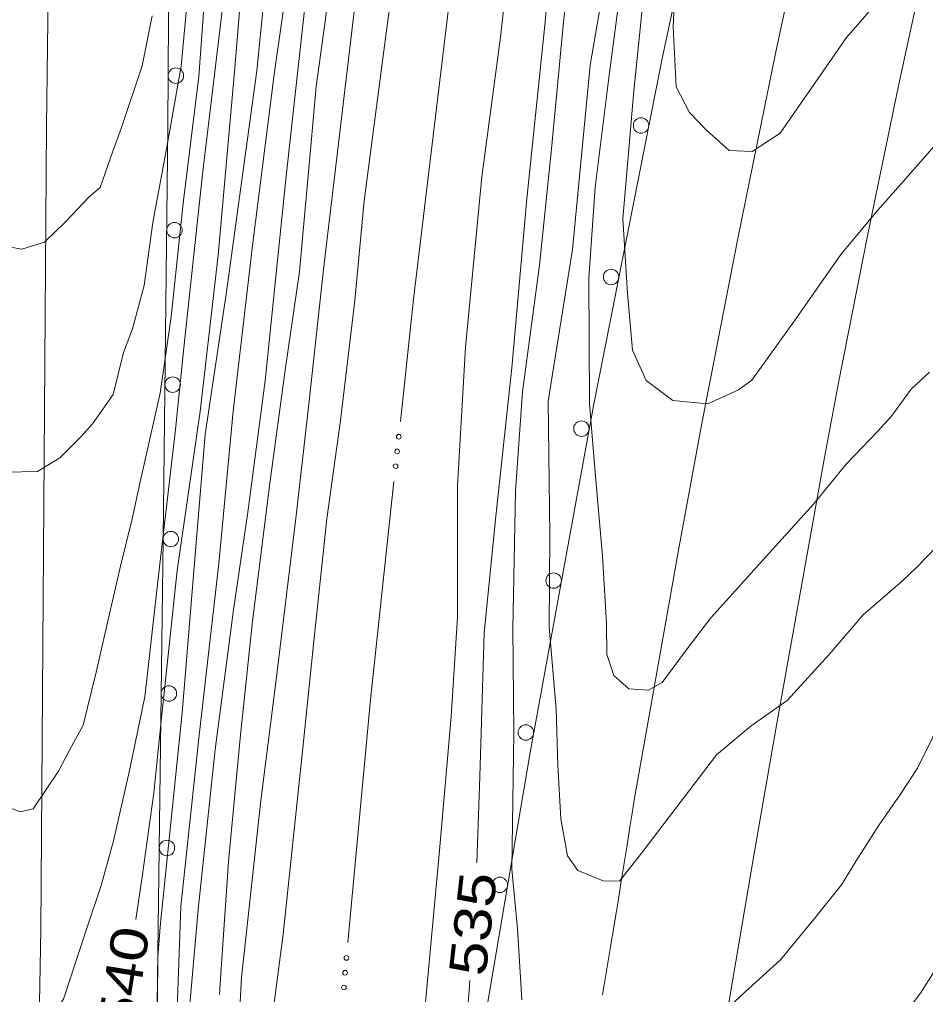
# Model space of a CAD drawing. Extents: x 2361284 to 2366480, y 6976556 to 6985346.
# Drawn here: x 2364474.8 to 2364592.1, y 6978408.5 to 6978534.7 of the extents above; entities that cross this region are included whole.
import ezdxf
from ezdxf.enums import TextEntityAlignment as Align

# ---------------------------------------------------------------- set-up
doc = ezdxf.new("R2010")
doc.units = 0
doc.header["$LTSCALE"] = 1.9
for name, color, linetype, lineweight in [('12', 7, 'Continuous', 13), ('13', 7, 'Continuous', 13), ('14', 7, 'Continuous', 13), ('17', 7, 'Continuous', 13), ('21', 7, 'Continuous', 13), ('3', 7, 'Continuous', 13)]:
    doc.layers.add(name, color=color, linetype=linetype, lineweight=lineweight)

msp = doc.modelspace()

# ---------------------------------------------------------------- linework, layer by layer
at = {"layer": '12'}
for points in [[(2364590.124, 6978796.473), (2364589.311, 6978793.616), (2364586.065, 6978781.543), (2364582.324, 6978764.768), (2364579.81, 6978751.442), (2364577.506, 6978732.98), (2364572.929, 6978712.785), (2364567.408, 6978685.481), (2364562.208, 6978655.901), (2364557.098, 6978625.39), (2364552.346, 6978600.353), (2364548.188, 6978577.113), (2364544.913, 6978557.55), (2364542.796, 6978533.969), (2364540.48, 6978511.486), (2364538.538, 6978489.626), (2364536.45, 6978470.414), (2364534.954, 6978455.27), (2364534.391, 6978436.674), (2364534.007, 6978425.489)], [(2364535.587, 6978743.233), (2364536.974, 6978737.144), (2364537.8, 6978722.852), (2364537.862, 6978705.811), (2364536.854, 6978695.091), (2364536.006, 6978686.533), (2364533.867, 6978665.382), (2364530.209, 6978635.716), (2364527.935, 6978616.122), (2364525.352, 6978597.457), (2364523.812, 6978581.63), (2364522.159, 6978564.185), (2364518.517, 6978539.078), (2364516.417, 6978521.208), (2364514.146, 6978502.345), (2364512.272, 6978484.886), (2364510.629, 6978470.469), (2364507.927, 6978448.502), (2364506.029, 6978433.584), (2364503.557, 6978410.64), (2364503.325, 6978406.647)], [(2364520.506, 6978735.888), (2364521.366, 6978731.636), (2364522.041, 6978723.722), (2364521.873, 6978713.01), (2364521.202, 6978704.803), (2364519.868, 6978691.46), (2364518.363, 6978678.275), (2364516.741, 6978664.799), (2364515.812, 6978651.079), (2364514.09, 6978638.611), (2364511.3, 6978619.744), (2364510.213, 6978597.243), (2364508.054, 6978577.141), (2364505.377, 6978557.884), (2364503.673, 6978540.488), (2364502.652, 6978527.957), (2364500.508, 6978504.195), (2364498.169, 6978483.972), (2364495.205, 6978463.383), (2364493.197, 6978444.292), (2364492.189, 6978434.553), (2364490.673, 6978423.687), (2364489.845, 6978418.159)], [(2364588.977, 6978540.589), (2364581.863, 6978532.4), (2364573.302, 6978519.989), (2364569.644, 6978517.604), (2364566.703, 6978517.736), (2364563.737, 6978520.368), (2364561.545, 6978522.667), (2364559.823, 6978525.99), (2364559.439, 6978533.787), (2364559.824, 6978542.732)], [(2364630.041, 6978541.409), (2364626.113, 6978529.581), (2364621.172, 6978517.023), (2364616.554, 6978502.098), (2364611.573, 6978484.27), (2364607.524, 6978469.281), (2364604.843, 6978459.045), (2364602.326, 6978447.1), (2364599.597, 6978433.284), (2364597.875, 6978424.076), (2364596.63, 6978419.294), (2364595.576, 6978416.524), (2364594.727, 6978414.336), (2364593.304, 6978411.563), (2364591.441, 6978408.625), (2364589.328, 6978405.834)], [(2364533.102, 6978410.281), (2364533.008, 6978408.979), (2364532.788, 6978406.379)]]:
    msp.add_lwpolyline(points, dxfattribs=at)
at = {"layer": '13'}
for points in [[(2364539.856, 6978407.775), (2364539.268, 6978416.999), (2364538.525, 6978424.672), (2364538.797, 6978442.385), (2364538.679, 6978455.856), (2364539.02, 6978473.66), (2364539.918, 6978486.509), (2364542.122, 6978502.901), (2364543.699, 6978517.987), (2364545.289, 6978534.842), (2364548.165, 6978556.391), (2364551.398, 6978579.073), (2364553.046, 6978586.639), (2364558.044, 6978612.148), (2364562.074, 6978637.429), (2364565.198, 6978653.839), (2364569.218, 6978674.988), (2364572.691, 6978692.602), (2364576.99, 6978711.574), (2364581.098, 6978731.754), (2364583.754, 6978746.931), (2364586.385, 6978763.626), (2364588.318, 6978773.935), (2364590.919, 6978788.541)], [(2364582.984, 6978780.554), (2364580.379, 6978769.43), (2364576.587, 6978750.812), (2364573.957, 6978736.106), (2364570.838, 6978720.207), (2364567.142, 6978699.83), (2364561.372, 6978672.302), (2364558.398, 6978655.884), (2364553.047, 6978628.662), (2364548.88, 6978607.382), (2364543.311, 6978577.796), (2364539.917, 6978558.062), (2364537.061, 6978532.444), (2364534.643, 6978514.34), (2364532.562, 6978492.269), (2364531.503, 6978474.349), (2364531.525, 6978457.318), (2364530.707, 6978444.469), (2364529.182, 6978427.093), (2364527.257, 6978406.534)], [(2364518.057, 6978768.387), (2364518.855, 6978766.494), (2364521.169, 6978759.735), (2364524.687, 6978750.488), (2364527.432, 6978743.715), (2364530.833, 6978734.076), (2364532.199, 6978721.908), (2364531.854, 6978712.945), (2364531.128, 6978696.817), (2364529.226, 6978679.108), (2364526.23, 6978658.639), (2364523.037, 6978629.497), (2364520.35, 6978610.32), (2364516.514, 6978581.462), (2364514.849, 6978568.325), (2364512.892, 6978546.936), (2364509.274, 6978514.049), (2364506.602, 6978487.942), (2364504.354, 6978470.939), (2364502.494, 6978458.262), (2364500.116, 6978440.189), (2364497.932, 6978419.476), (2364496.688, 6978405.203), (2364495.468, 6978383.211)], [(2364516.737, 6978767.264), (2364516.712, 6978765.734), (2364518.098, 6978761.887), (2364520.11, 6978756.455), (2364522.655, 6978749.589), (2364525.242, 6978742.654), (2364527.63, 6978733.405), (2364527.554, 6978723.504), (2364527.981, 6978712.218), (2364526.793, 6978697.246), (2364525.485, 6978677.082), (2364522.555, 6978657.094), (2364520.874, 6978638.276), (2364518.005, 6978615.998), (2364515.456, 6978596.953), (2364512.724, 6978567.745), (2364510.081, 6978543.849), (2364507.792, 6978527.946), (2364504.976, 6978505.468), (2364502.48, 6978483.983), (2364500.617, 6978464.274), (2364498.011, 6978441.668), (2364495.689, 6978419.875), (2364495.109, 6978404.108)], [(2364518.132, 6978734.125), (2364518.237, 6978733.596), (2364519.017, 6978721.054), (2364518.808, 6978712.451), (2364517.296, 6978700.106), (2364516.842, 6978687.881), (2364515.589, 6978676.578), (2364511.021, 6978641.672), (2364508.322, 6978621.586), (2364506.358, 6978602.046), (2364504.043, 6978573.053), (2364503.093, 6978553.113), (2364498.487, 6978514.706), (2364496.091, 6978492.183), (2364494.992, 6978481.632), (2364492.921, 6978463.861), (2364491.011, 6978446.991), (2364488.935, 6978437.082), (2364486.948, 6978428.352), (2364485.353, 6978422.576), (2364483.447, 6978416.898), (2364480.503, 6978407.861), (2364478.063, 6978404.696), (2364472.797, 6978399.876)], [(2364523.671, 6978734.298), (2364524.348, 6978730.444), (2364524.188, 6978715.642), (2364524.08, 6978700.74), (2364521.906, 6978682.249), (2364519.342, 6978661.613), (2364517.054, 6978639.24), (2364514.257, 6978618.932), (2364512.3, 6978603.913), (2364510.193, 6978581.521), (2364508.277, 6978555.881), (2364505.541, 6978528.054), (2364501.603, 6978499.455), (2364498.818, 6978480.958), (2364497.606, 6978466.416), (2364495.85, 6978444.937), (2364493.07, 6978417.7), (2364492.691, 6978413.396), (2364492.618, 6978402.145), (2364490.71, 6978385.377), (2364490.168, 6978383.619), (2364490.043, 6978384.74)], [(2364516.853, 6978554.233), (2364514.334, 6978534.138), (2364513.19, 6978526.057), (2364512.56, 6978518.781), (2364511.028, 6978502.085), (2364509.2, 6978489.287), (2364507.256, 6978474.958), (2364504.978, 6978456.816), (2364503.388, 6978442.099), (2364501.834, 6978425.703), (2364500.906, 6978411.775), (2364500.668, 6978408.462)], [(2364594.839, 6978467.78), (2364590.967, 6978463.793), (2364589.123, 6978462.046), (2364584.034, 6978457.607), (2364579.614, 6978452.475), (2364574.2, 6978446.552), (2364569.521, 6978443.268), (2364565.056, 6978439.486), (2364555.484, 6978426.973), (2364552.491, 6978423.125), (2364550.361, 6978423.165), (2364547.098, 6978424.514), (2364545.73, 6978426.431), (2364544.875, 6978431.204), (2364544.498, 6978438.16), (2364544.27, 6978445.398), (2364543.369, 6978456.021), (2364543.445, 6978467.922), (2364543.26, 6978485.291), (2364546.404, 6978504.922), (2364548.687, 6978528.814), (2364552.05, 6978548.418)], [(2364524.217, 6978547.504), (2364522.162, 6978532.302), (2364519.401, 6978511.255), (2364518.194, 6978498.313), (2364516.372, 6978482.785), (2364514.573, 6978470.046), (2364512.923, 6978454.231), (2364511.429, 6978439.956), (2364508.954, 6978416.281), (2364507.648, 6978406.378)], [(2364627.866, 6978547.149), (2364622.261, 6978529.784), (2364618.582, 6978518.099), (2364612.854, 6978499.943), (2364608.902, 6978486.415), (2364606.064, 6978477.888), (2364601.895, 6978463.997), (2364600.498, 6978459.544), (2364599.208, 6978455.351), (2364597.514, 6978451.495), (2364595.346, 6978447.123), (2364592.929, 6978441.521), (2364591.084, 6978437.783), (2364588.866, 6978434.402), (2364586.123, 6978430.416), (2364583.147, 6978425.766), (2364581.226, 6978422.668), (2364577.887, 6978418.496), (2364573.349, 6978412.964), (2364568.749, 6978408.82), (2364565.308, 6978405.576)], [(2364499.328, 6978545.147), (2364498.016, 6978527.343), (2364495.982, 6978510.942), (2364494.433, 6978496.208), (2364493.017, 6978486.333), (2364490.416, 6978474.838), (2364489.362, 6978470.077), (2364487.87, 6978463.913), (2364486.573, 6978458.311), (2364484.72, 6978450.182), (2364483.026, 6978443.325), (2364481.256, 6978440.109), (2364479.852, 6978437.366), (2364476.547, 6978432.484), (2364474.881, 6978432.098), (2364471.247, 6978433.554)], [(2364592.627, 6978489.03), (2364590.258, 6978486.858), (2364587.691, 6978483.363), (2364585.928, 6978481.406), (2364581.838, 6978477.157), (2364577.619, 6978471.966), (2364574.343, 6978468.316), (2364570.641, 6978464.28), (2364564.297, 6978457.24), (2364561.245, 6978453.23), (2364557.986, 6978448.848), (2364556.216, 6978447.881), (2364553.694, 6978448.027), (2364551.737, 6978449.789), (2364550.853, 6978452.482), (2364550.784, 6978456.521), (2364550.302, 6978465.207), (2364549.274, 6978476.558), (2364548.603, 6978485.012), (2364548.519, 6978501.222), (2364549.327, 6978513.02), (2364551.045, 6978526.827), (2364553.302, 6978544)], [(2364610.54, 6978536.113), (2364607.196, 6978531.181), (2364605.903, 6978529.488), (2364603.277, 6978526.923), (2364599.659, 6978523.55), (2364597.234, 6978521.937), (2364594.465, 6978519.76), (2364589.538, 6978514.122), (2364585.926, 6978510.028), (2364581.141, 6978504.272), (2364575.212, 6978495.816), (2364569.616, 6978488.012), (2364567.887, 6978486.775), (2364563.913, 6978484.957), (2364559.399, 6978485.364), (2364555.954, 6978487.992), (2364554.157, 6978491.915), (2364553.497, 6978499.279), (2364552.915, 6978508.904), (2364554.348, 6978525.479), (2364555.919, 6978541.145)], [(2364496.813, 6978540.333), (2364495.724, 6978528.691), (2364493.912, 6978518.424), (2364492.067, 6978508.445), (2364490.935, 6978500.264), (2364489.418, 6978494.659), (2364488.277, 6978491.578), (2364486.928, 6978486.175), (2364484.225, 6978482.359), (2364482.73, 6978480.685), (2364480.016, 6978477.959), (2364477.113, 6978476.191), (2364472.992, 6978476.112)], [(2364491.983, 6978535.176), (2364490.654, 6978528.713), (2364487.941, 6978520.587), (2364486.879, 6978517.667), (2364485.234, 6978512.97), (2364483.795, 6978511.757), (2364480.755, 6978508.538), (2364478.031, 6978505.882), (2364475.088, 6978504.964), (2364473.395, 6978505.267)]]:
    msp.add_lwpolyline(points, dxfattribs=at)
at = {"layer": '14'}
msp.add_lwpolyline([(2364768.994, 6979219.127), (2364752.068, 6979153.983), (2364743.532, 6979121.43), (2364698.712, 6978951.934), (2364666.156, 6978828.159), (2364661.788, 6978811.837), (2364652.77, 6978779.27), (2364634.378, 6978714.23), (2364625.447, 6978681.633), (2364622.028, 6978668.681), (2364615.422, 6978642.721), (2364609.085, 6978616.695), (2364604.985, 6978599.313), (2364597.02, 6978564.487), (2364591.358, 6978538.927), (2364588.607, 6978526.132), (2364584.62, 6978506.912), (2364580.84, 6978487.651), (2364579.041, 6978478.001), (2364572.904, 6978443.823), (2364569.919, 6978426.721), (2364565.552, 6978401.048), (2364559.651, 6978365.3)], dxfattribs=at)
at = {"layer": '17'}
for points in [[(2364529.965, 6978373.138), (2364535.258, 6978406.49), (2364540.902, 6978439.786), (2364549.106, 6978484.686), (2364557.97, 6978529.463), (2364569.459, 6978583.334), (2364582.179, 6978636.93), (2364594.237, 6978683.576), (2364606.935, 6978730.039), (2364617.539, 6978767.613), (2364628.223, 6978805.166), (2364632.657, 6978820.549), (2364637.071, 6978835.932), (2364663.548, 6978929.949), (2364689.975, 6979023.985), (2364706.14, 6979080.432), (2364722.184, 6979136.917), (2364728.188, 6979158.586), (2364734.162, 6979180.253), (2364740.454, 6979203.114), (2364746.738, 6979225.977)], [(2364481.734, 6978800.063), (2364481.337, 6978771.288), (2364480.961, 6978742.503), (2364481.215, 6978733.674), (2364482.009, 6978724.851), (2364483.864, 6978710.658), (2364486.198, 6978696.54), (2364489.164, 6978682.307), (2364492.079, 6978668.063), (2364493.286, 6978659.956), (2364494.103, 6978651.793), (2364494.898, 6978638.669), (2364495.303, 6978625.542), (2364495.462, 6978609.883), (2364495.33, 6978594.231), (2364494.728, 6978578.725), (2364494.206, 6978563.219), (2364494.118, 6978541.997), (2364494.01, 6978520.785), (2364493.703, 6978494.12), (2364493.387, 6978467.456), (2364493.013, 6978437.301), (2364492.62, 6978407.146)]]:
    msp.add_lwpolyline(points, dxfattribs=at)
for centre in [(2364495.043, 6978527.439), (2364555.275, 6978520.997), (2364494.857, 6978507.434), (2364551.391, 6978501.378), (2364494.624, 6978487.434), (2364547.551, 6978481.735), (2364494.386, 6978467.435), (2364543.956, 6978462.061), (2364494.137, 6978447.436), (2364540.361, 6978442.386), (2364493.883, 6978427.437), (2364536.986, 6978422.66)]:
    msp.add_circle(centre, 1, dxfattribs=at)
at = {"layer": '21'}
for points in [[(2364524.113, 6978482.679), (2364525.813, 6978498.516), (2364531.087, 6978542.269)], [(2364517.315, 6978415.18), (2364520.255, 6978446.669), (2364523.278, 6978474.88)]]:
    msp.add_lwpolyline(points, dxfattribs=at)
for centre in [(2364523.901, 6978480.692), (2364523.697, 6978478.783), (2364523.492, 6978476.874), (2364517.127, 6978413.192), (2364516.956, 6978411.28), (2364516.796, 6978409.366)]:
    msp.add_circle(centre, 0.3, dxfattribs=at)
at = {"layer": '3'}
for points in [[(2364633.797, 6978777.358), (2364623.411, 6978739.013), (2364616.666, 6978713.407), (2364612.239, 6978696.317), (2364603.532, 6978662.094), (2364594.771, 6978626.783), (2364590.495, 6978609.106), (2364584.241, 6978582.552), (2364578.214, 6978555.941), (2364575.297, 6978542.609), (2364572.728, 6978530.544), (2364567.797, 6978506.379), (2364563.117, 6978482.168), (2364560.121, 6978466.004), (2364554.381, 6978433.624)], [(2364482.094, 6978724.262), (2364481.508, 6978716.488), (2364481.201, 6978711.305), (2364480.756, 6978700.94), (2364480.398, 6978685.392), (2364480.08, 6978654.29), (2364478.832, 6978565.328), (2364478.308, 6978520.846), (2364477.537, 6978416.872), (2364477.188, 6978397.733), (2364476.86, 6978388.164)], [(2364554.381, 6978433.624), (2364554.197, 6978432.46), (2364553.828, 6978430.131), (2364553.457, 6978427.803), (2364553.209, 6978426.251), (2364552.709, 6978423.148), (2364552.332, 6978420.821), (2364552.08, 6978419.27), (2364551.574, 6978416.167), (2364551.319, 6978414.617), (2364550.808, 6978411.515), (2364550.295, 6978408.414)]]:
    msp.add_lwpolyline(points, dxfattribs=at)

# ---------------------------------------------------------------- texts
at = {"layer": '12', "width": 1.25}
for s, rotation, p in [(' 535 ', 83.561, (2364535.88, 6978417.345)), (' 540 ', 80.994, (2364490.629, 6978410.189))]:
    msp.add_text(s, height=4.8, rotation=rotation, dxfattribs=at).set_placement(p, align=Align.CENTER)

doc.saveas('drawing.dxf')
